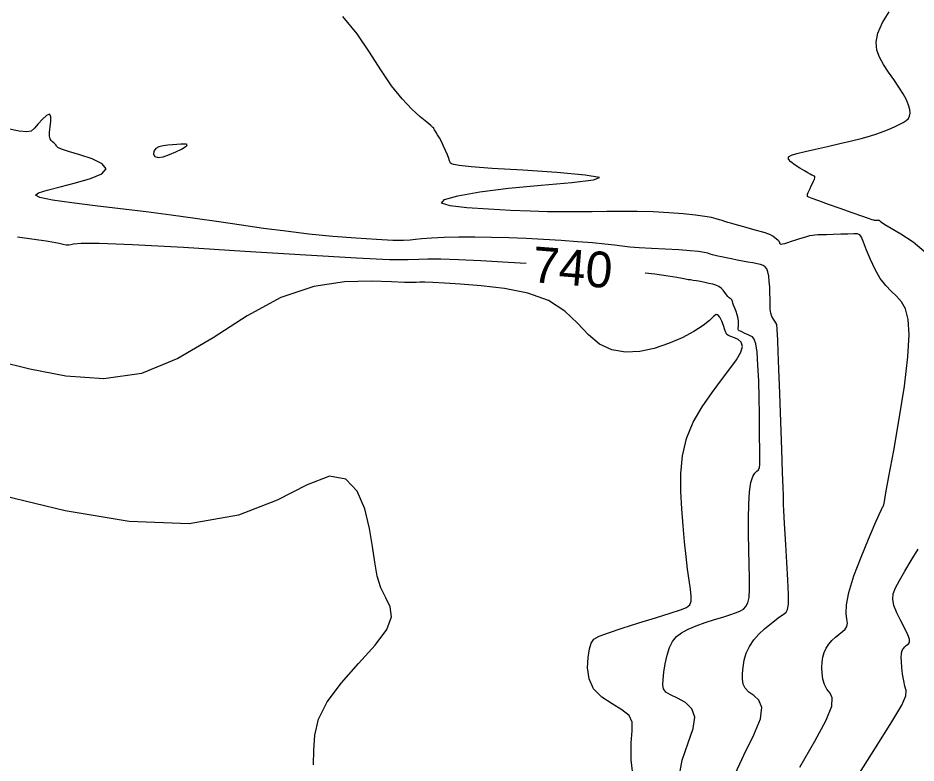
# Model space of a CAD drawing. Extents: x 2566142 to 2571431, y 418755 to 421584.
# Drawn here: x 2568835 to 2569337, y 419171 to 419587 of the extents above; entities that cross this region are included whole.
import ezdxf

# ---------------------------------------------------------------- set-up
doc = ezdxf.new("R2010")
doc.units = 0
for name, color, linetype in [('Contour_ADS_Label_Major', 7, 'Continuous'), ('Contour_ADS_Major', 7, 'Continuous'), ('Contour_ADS_Minor', 7, 'Continuous')]:
    doc.layers.add(name, color=color, linetype=linetype)

msp = doc.modelspace()

# ---------------------------------------------------------------- linework, layer by layer
at = {"layer": 'Contour_ADS_Major'}
for points in [[(2569118.99, 419449.78), (2569109.17, 419450.42), (2569093.74, 419451.32), (2569081.11, 419451.92), (2569071.25, 419452.23), (2569064.09, 419452.25), (2569059, 419452.02), (2569053.04, 419451.82), (2569042.65, 419451.97), (2569024.29, 419452.79), (2568995.96, 419454.45), (2568961.85, 419456.6), (2568927.68, 419458.72), (2568899.18, 419460.31), (2568880.63, 419460.99), (2568870.61, 419460.98), (2568866.27, 419460.6), (2568864.73, 419460.2), (2568863.6, 419460.06), (2568862.26, 419460.18), (2568860.55, 419460.5), (2568858.33, 419460.99), (2568855.34, 419461.6), (2568850.94, 419462.36), (2568844.39, 419463.33), (2568834.95, 419464.57)], [(2569200.67, 419238.82), (2569202.85, 419241.51), (2569205.68, 419243.69), (2569209.33, 419245.62), (2569213.87, 419247.5), (2569218.93, 419249.31), (2569224.04, 419250.98), (2569228.75, 419252.44), (2569232.66, 419253.64), (2569235.81, 419254.69), (2569238.29, 419255.71), (2569240.21, 419256.83), (2569241.68, 419258.23), (2569242.73, 419260.28), (2569243.4, 419263.37), (2569243.71, 419267.9), (2569243.73, 419274.14), (2569243.55, 419281.72), (2569243.29, 419290.15), (2569243.09, 419298.91), (2569243.03, 419307.51), (2569243.2, 419315.46), (2569243.63, 419322.29), (2569244.37, 419327.53), (2569245.43, 419330.89), (2569246.64, 419332.79), (2569247.82, 419333.86), (2569248.74, 419334.72), (2569249.26, 419335.9), (2569249.45, 419337.61), (2569249.45, 419339.95), (2569249.38, 419343.06), (2569249.34, 419347.05), (2569249.32, 419352.08), (2569249.29, 419358.32), (2569249.2, 419365.95), (2569249.04, 419374.91), (2569248.78, 419384.34), (2569248.39, 419393.16), (2569247.87, 419400.29), (2569247.19, 419404.96), (2569246.33, 419407.58), (2569245.28, 419408.86), (2569244.03, 419409.53), (2569242.57, 419410.17), (2569241.06, 419410.84), (2569239.66, 419411.47), (2569238.54, 419411.98), (2569237.82, 419412.34), (2569237.45, 419412.64), (2569237.33, 419413.03), (2569237.39, 419413.65), (2569237.51, 419414.61), (2569237.6, 419415.88), (2569237.57, 419417.43), (2569237.33, 419419.2), (2569236.81, 419421.13), (2569236.13, 419423.1), (2569235.41, 419424.94), (2569234.81, 419426.51), (2569234.42, 419427.7), (2569234.18, 419428.55), (2569233.99, 419429.15), (2569233.75, 419429.57), (2569233.36, 419429.89), (2569232.85, 419430.23), (2569232.24, 419430.71), (2569231.54, 419431.42), (2569230.79, 419432.45), (2569229.95, 419433.68), (2569228.97, 419434.95), (2569227.83, 419436.1), (2569226.48, 419437), (2569224.9, 419437.7), (2569223.09, 419438.26), (2569221.02, 419438.76), (2569218.72, 419439.25), (2569216.36, 419439.72), (2569214.13, 419440.13), (2569212.23, 419440.45), (2569210.76, 419440.65), (2569209.48, 419440.82), (2569208.01, 419441.04), (2569206.02, 419441.41), (2569203.05, 419442.01), (2569198.26, 419442.84), (2569190.73, 419443.87), (2569185.45, 419444.45)], [(2569203.93, 419161.21), (2569206.14, 419172.49), (2569209.32, 419182.14), (2569212.11, 419190.14), (2569213.15, 419196.49), (2569211.48, 419201.21), (2569207.88, 419204.61), (2569203.51, 419207.05), (2569199.57, 419208.9), (2569196.98, 419210.51), (2569195.65, 419212.25), (2569195.25, 419214.46), (2569195.43, 419217.49), (2569195.9, 419221.56), (2569196.64, 419226.26), (2569197.66, 419231.05), (2569198.99, 419235.37), (2569200.67, 419238.82)]]:
    msp.add_lwpolyline(points, dxfattribs=at)
at = {"layer": 'Contour_ADS_Minor'}
for points in [[(2569318.23, 419523.57), (2569321.54, 419524.88), (2569324.57, 419526.2), (2569327.22, 419527.48), (2569329.44, 419528.68), (2569331.14, 419529.79), (2569332.34, 419530.92), (2569333.06, 419532.21), (2569333.33, 419533.8), (2569333.14, 419535.8), (2569332.46, 419538.26), (2569331.23, 419541.18), (2569329.4, 419544.56), (2569326.97, 419548.4), (2569324.15, 419552.53), (2569321.23, 419556.78), (2569318.48, 419560.96), (2569316.2, 419564.99), (2569314.68, 419569.06), (2569314.28, 419573.48), (2569315.31, 419578.54), (2569317.93, 419584.37), (2569321.59, 419590.46)], [(2569097.87, 419480.13), (2569085.9, 419480.97), (2569076.47, 419482.11), (2569071.74, 419483.62), (2569073.35, 419485.51), (2569080.8, 419487.64), (2569093.04, 419489.82), (2569109.05, 419491.86), (2569127.32, 419493.61), (2569144.45, 419495.14), (2569156.59, 419496.53), (2569159.88, 419497.88), (2569151.91, 419499.26), (2569136.05, 419500.62), (2569117.12, 419501.89), (2569099.95, 419503), (2569088.28, 419503.89), (2569081.64, 419504.59), (2569078.51, 419505.12), (2569077.34, 419505.54), (2569076.82, 419505.91), (2569076.53, 419506.4), (2569076.26, 419507.21), (2569075.82, 419508.54), (2569075.04, 419510.51), (2569074.01, 419512.91), (2569072.84, 419515.47), (2569071.64, 419517.9), (2569070.53, 419519.97), (2569069.55, 419521.64), (2569068.74, 419522.94), (2569068.14, 419523.87), (2569067.77, 419524.47), (2569067.57, 419524.81), (2569067.49, 419525), (2569067.47, 419525.14), (2569067.4, 419525.34), (2569066.95, 419525.85), (2569065.77, 419526.92), (2569063.5, 419528.82), (2569059.89, 419531.8), (2569055.18, 419536.05), (2569049.73, 419541.74), (2569043.89, 419549.04), (2569037.91, 419557.97), (2569031.59, 419567.92), (2569024.6, 419578.12), (2569016.63, 419587.8)], [(2568892.59, 419480.42), (2568878.39, 419482.13), (2568865.29, 419483.77), (2568854.58, 419485.31), (2568847.53, 419486.74), (2568845.09, 419488.07), (2568846.73, 419489.41), (2568851.6, 419490.9), (2568858.82, 419492.68), (2568867.38, 419494.83), (2568875.68, 419497.31), (2568882, 419500), (2568884.59, 419502.8), (2568882.36, 419505.6), (2568876.72, 419508.25), (2568869.74, 419510.59), (2568863.49, 419512.46), (2568859.55, 419513.76), (2568857.62, 419514.6), (2568856.94, 419515.16), (2568856.75, 419515.61), (2568856.42, 419516.1), (2568855.88, 419516.64), (2568855.21, 419517.22), (2568854.49, 419517.83), (2568853.81, 419518.51), (2568853.26, 419519.46), (2568852.92, 419520.91), (2568852.9, 419523.11), (2568853.21, 419526.14), (2568853.55, 419529.37), (2568853.57, 419532), (2568852.89, 419533.22), (2568851.28, 419532.52), (2568849.05, 419530.43), (2568846.61, 419527.77), (2568844.42, 419525.35), (2568842.62, 419523.84), (2568840.24, 419523.34), (2568836.02, 419523.8), (2568828.71, 419525.17)], [(2569342.32, 419455.62), (2569334.98, 419461.78), (2569328.18, 419466.27), (2569322.73, 419469.41), (2569319.22, 419471.46), (2569317.36, 419472.68), (2569316.61, 419473.32), (2569316.42, 419473.62), (2569316.36, 419473.77), (2569316.31, 419473.85), (2569316.24, 419473.88), (2569316.12, 419473.88), (2569315.93, 419473.87), (2569315.67, 419473.87), (2569315.37, 419473.86), (2569315.02, 419473.86), (2569314.65, 419473.86), (2569314.27, 419473.87), (2569313.88, 419473.89), (2569313.5, 419473.93), (2569313.05, 419474.02), (2569312.08, 419474.32), (2569310.05, 419475.01), (2569306.42, 419476.29), (2569300.92, 419478.23), (2569294.35, 419480.55), (2569287.79, 419482.88), (2569282.31, 419484.82), (2569278.72, 419486.09), (2569276.8, 419486.86), (2569276.03, 419487.36), (2569275.94, 419487.85), (2569276.11, 419488.54), (2569276.44, 419489.44), (2569276.91, 419490.55), (2569277.48, 419491.81), (2569278.15, 419493.21), (2569278.82, 419494.62), (2569279.42, 419495.91), (2569279.88, 419496.96), (2569280.13, 419497.68), (2569280.21, 419498.1), (2569280.16, 419498.33), (2569280.05, 419498.45), (2569279.92, 419498.54), (2569279.73, 419498.64), (2569279.46, 419498.77), (2569279.07, 419498.96), (2569278.49, 419499.25), (2569277.61, 419499.72), (2569276.28, 419500.45), (2569274.36, 419501.55), (2569271.81, 419503.05), (2569269.09, 419504.78), (2569266.76, 419506.54), (2569265.4, 419508.11), (2569265.47, 419509.36), (2569267.05, 419510.38), (2569270.12, 419511.35), (2569274.65, 419512.44), (2569280.52, 419513.76), (2569287.21, 419515.26), (2569294.08, 419516.82), (2569300.51, 419518.34), (2569306.01, 419519.74), (2569310.65, 419521.05), (2569314.65, 419522.31), (2569318.23, 419523.57)], [(2569254.95, 419248.27), (2569257.52, 419250.29), (2569259.7, 419251.92), (2569261.51, 419253.2), (2569262.98, 419254.21), (2569264.13, 419255.13), (2569264.94, 419256.68), (2569265.39, 419259.7), (2569265.45, 419265.03), (2569265.13, 419273.11), (2569264.56, 419282.89), (2569263.9, 419292.88), (2569263.33, 419301.64), (2569262.97, 419308.03), (2569262.78, 419312.29), (2569262.71, 419314.97), (2569262.69, 419316.62), (2569262.66, 419317.95), (2569262.58, 419320.22), (2569262.41, 419324.81), (2569262.11, 419333.12), (2569261.66, 419345.92), (2569261.12, 419361.42), (2569260.56, 419377.21), (2569260.06, 419390.88), (2569259.66, 419400.6), (2569259.38, 419406.78), (2569259.19, 419410.42), (2569259.1, 419412.53), (2569259.06, 419413.94), (2569259, 419414.99), (2569258.83, 419415.83), (2569258.44, 419416.64), (2569257.79, 419417.58), (2569256.98, 419418.75), (2569256.19, 419420.23), (2569255.57, 419422.11), (2569255.23, 419424.44), (2569255.12, 419427.16), (2569255.11, 419430.17), (2569255.09, 419433.38), (2569254.97, 419436.68), (2569254.72, 419439.88), (2569254.36, 419442.77), (2569253.89, 419445.13), (2569253.28, 419446.84), (2569252.46, 419447.98), (2569251.34, 419448.73), (2569249.84, 419449.27), (2569247.88, 419449.74), (2569245.51, 419450.19), (2569242.8, 419450.66), (2569239.83, 419451.18), (2569236.69, 419451.77), (2569233.55, 419452.39), (2569230.6, 419453), (2569228.05, 419453.54), (2569226.02, 419453.98), (2569224.4, 419454.36), (2569223.04, 419454.72), (2569221.76, 419455.1), (2569220.34, 419455.54), (2569218.34, 419456.03), (2569215.27, 419456.52), (2569210.62, 419456.99), (2569204.15, 419457.4), (2569196.59, 419457.79), (2569188.92, 419458.17), (2569182.13, 419458.58), (2569176.88, 419459.04), (2569172.56, 419459.54), (2569168.23, 419460.1), (2569162.95, 419460.71), (2569156.04, 419461.35), (2569147.71, 419462.01), (2569138.45, 419462.65), (2569128.72, 419463.24), (2569118.93, 419463.75), (2569109.22, 419464.16), (2569099.67, 419464.44), (2569090.35, 419464.55), (2569081.41, 419464.5), (2569073.22, 419464.29), (2569066.21, 419463.98), (2569060.81, 419463.59), (2569057.16, 419463.17), (2569054.16, 419462.83), (2569050.41, 419462.65), (2569044.51, 419462.74), (2569035.47, 419463.19), (2569023.93, 419463.96), (2569010.98, 419465.02), (2568997.66, 419466.32), (2568984.81, 419467.83), (2568972.36, 419469.49), (2568959.98, 419471.26), (2568947.37, 419473.09), (2568934.27, 419474.95), (2568920.72, 419476.8), (2568906.79, 419478.63), (2568892.59, 419480.42)], [(2569298.07, 419251.15), (2569297.64, 419254.38), (2569297.73, 419259.17), (2569299.03, 419266.08), (2569301.95, 419275.35), (2569305.92, 419285.8), (2569310.11, 419295.94), (2569313.69, 419304.26), (2569316.04, 419309.63), (2569317.32, 419312.51), (2569317.87, 419313.71), (2569318.07, 419314.05), (2569318.2, 419314.23), (2569318.32, 419314.4), (2569318.41, 419314.54), (2569318.49, 419314.68), (2569318.59, 419315.06), (2569318.93, 419316.9), (2569319.82, 419321.7), (2569321.51, 419330.93), (2569324.15, 419345.38), (2569327.23, 419363.09), (2569330.11, 419381.44), (2569332.13, 419397.77), (2569332.78, 419410.05), (2569332.2, 419418.64), (2569330.66, 419424.47), (2569328.42, 419428.51), (2569325.74, 419431.64), (2569322.78, 419434.47), (2569319.7, 419437.56), (2569316.64, 419441.44), (2569313.74, 419446.44), (2569311.14, 419452.01), (2569308.95, 419457.36), (2569307.3, 419461.71), (2569306.21, 419464.47), (2569305.28, 419465.89), (2569304.01, 419466.38), (2569301.89, 419466.39), (2569298.61, 419466.28), (2569294.58, 419466.15), (2569290.41, 419466.02), (2569286.68, 419465.91), (2569283.86, 419465.85), (2569281.8, 419465.79), (2569280.19, 419465.7), (2569278.74, 419465.52), (2569277.2, 419465.23), (2569275.5, 419464.81), (2569273.62, 419464.27), (2569271.54, 419463.61), (2569269.27, 419462.85), (2569266.98, 419462.08), (2569264.88, 419461.38), (2569263.18, 419460.86), (2569262.02, 419460.59), (2569261.32, 419460.54), (2569260.95, 419460.64), (2569260.76, 419460.84), (2569260.65, 419461.1), (2569260.58, 419461.37), (2569260.53, 419461.62), (2569260.49, 419461.83), (2569260.44, 419461.99), (2569260.31, 419462.16), (2569260.03, 419462.42), (2569259.54, 419462.85), (2569258.79, 419463.49), (2569257.8, 419464.28), (2569256.64, 419465.11), (2569255.35, 419465.87), (2569253.96, 419466.49), (2569252.32, 419467.03), (2569250.26, 419467.61), (2569247.6, 419468.32), (2569244.26, 419469.22), (2569240.57, 419470.24), (2569236.96, 419471.26), (2569233.85, 419472.15), (2569231.55, 419472.83), (2569229.85, 419473.36), (2569228.42, 419473.81), (2569226.93, 419474.29), (2569225.05, 419474.86), (2569222.42, 419475.5), (2569218.69, 419476.18), (2569213.51, 419476.88), (2569206.69, 419477.55), (2569198.61, 419478.15), (2569189.84, 419478.62), (2569180.93, 419478.91), (2569172.31, 419478.98), (2569163.98, 419478.9), (2569155.83, 419478.77), (2569147.74, 419478.66), (2569139.53, 419478.67), (2569130.83, 419478.8), (2569121.2, 419479.08), (2569110.21, 419479.52), (2569097.87, 419480.13)], [(2569161.27, 419207.71), (2569156.65, 419212.31), (2569154.08, 419217.94), (2569153.24, 419224.03), (2569153.52, 419229.85), (2569154.31, 419234.64), (2569155.2, 419237.91), (2569156.74, 419240.07), (2569159.7, 419241.76), (2569164.85, 419243.64), (2569172.57, 419246.17), (2569181.84, 419249.11), (2569191.22, 419252.05), (2569199.32, 419254.56), (2569205.04, 419256.36), (2569208.57, 419257.78), (2569210.43, 419259.25), (2569211.13, 419261.25), (2569211.14, 419264.14), (2569210.69, 419268.05), (2569209.94, 419273.03), (2569209.06, 419279.11), (2569208.21, 419286.3), (2569207.4, 419294.44), (2569206.65, 419303.34), (2569205.95, 419312.78), (2569205.39, 419322.58), (2569205.32, 419332.52), (2569206.18, 419342.41), (2569208.4, 419352.05), (2569212.25, 419361.26), (2569217.24, 419369.88), (2569222.74, 419377.79), (2569228.1, 419384.86), (2569232.74, 419390.99), (2569236.36, 419396.15), (2569238.75, 419400.34), (2569239.67, 419403.56), (2569239.05, 419405.85), (2569237.35, 419407.39), (2569235.2, 419408.39), (2569233.21, 419409.05), (2569231.86, 419409.6), (2569231.04, 419410.26), (2569230.47, 419411.27), (2569229.89, 419412.86), (2569229.11, 419415.14), (2569228.15, 419417.67), (2569227.1, 419419.9), (2569226.05, 419421.27), (2569225, 419421.34), (2569223.58, 419420.21), (2569221.32, 419418.11), (2569217.75, 419415.26), (2569212.56, 419411.91), (2569206.01, 419408.42), (2569198.52, 419405.15), (2569190.51, 419402.47), (2569182.37, 419400.76), (2569174.4, 419400.34), (2569166.84, 419401.57), (2569159.96, 419404.76), (2569153.82, 419410.04), (2569147.66, 419416.56), (2569140.52, 419423.27), (2569131.43, 419429.1), (2569119.84, 419433.25), (2569106.81, 419435.89), (2569093.79, 419437.43), (2569082.26, 419438.31), (2569073.35, 419438.87), (2569066.92, 419439.21), (2569062.48, 419439.37), (2569059.58, 419439.38), (2569057.56, 419439.3), (2569055.2, 419439.22), (2569051.09, 419439.27), (2569043.82, 419439.6), (2569032.42, 419440.07), (2569017.57, 419439.65), (2569000.39, 419437.02), (2568981.98, 419430.9), (2568963.25, 419420.66), (2568944.18, 419408.36), (2568924.58, 419396.71), (2568904.23, 419388.43), (2568883.12, 419385.51), (2568862.01, 419386.88), (2568841.88, 419390.76), (2568823.69, 419395.34)], [(2569035.85, 419275.26), (2569034.5, 419282.99), (2569033.23, 419291.88), (2569031.52, 419301.94), (2569028.84, 419312.79), (2569024.61, 419322.67), (2569018.23, 419329.46), (2569009.12, 419331.03), (2568996.65, 419326.24), (2568980, 419317.77), (2568958.32, 419309.26), (2568930.76, 419304.39), (2568897.35, 419305.74), (2568861.55, 419311.78), (2568827.75, 419319.9)], [(2569331.94, 419237.09), (2569332.61, 419237.7), (2569333.01, 419238.57), (2569332.88, 419240.04), (2569332.01, 419242.46), (2569330.29, 419246.01), (2569328.1, 419250.31), (2569325.94, 419254.8), (2569324.31, 419258.94), (2569323.61, 419262.35), (2569323.91, 419265.43), (2569325.15, 419268.72), (2569327.3, 419272.78), (2569330.28, 419277.99), (2569333.86, 419284.02), (2569337.78, 419290.32)], [(2569000.19, 419169.92), (2569000.36, 419178.04), (2569000.94, 419186.44), (2569003.05, 419195.38), (2569007.81, 419205.1), (2569015.81, 419215.66), (2569025.46, 419226.44), (2569034.66, 419236.65), (2569041.28, 419245.5), (2569043.81, 419252.45), (2569043.1, 419258.08), (2569040.62, 419263.22), (2569037.83, 419268.72), (2569035.85, 419275.26)], [(2569271.7, 419168.54), (2569280.09, 419183.01), (2569286.51, 419194.75), (2569289.56, 419202.56), (2569289.89, 419207.21), (2569288.6, 419209.98), (2569286.82, 419212.15), (2569285.48, 419214.73), (2569284.65, 419217.75), (2569284.24, 419220.99), (2569284.12, 419224.22), (2569284.23, 419227.25), (2569284.59, 419230.05), (2569285.28, 419232.65), (2569286.36, 419235.06), (2569287.88, 419237.29), (2569289.7, 419239.34), (2569291.68, 419241.19), (2569293.66, 419242.83), (2569295.48, 419244.28), (2569296.98, 419245.67), (2569298, 419247.16), (2569298.37, 419248.91), (2569298.07, 419251.15)], [(2569234.66, 419162.77), (2569240.51, 419175.34), (2569246.1, 419186.58), (2569249.83, 419195.62), (2569250.52, 419201.88), (2569248.88, 419205.91), (2569246.06, 419208.52), (2569243.2, 419210.52), (2569241.23, 419212.62), (2569240.15, 419215), (2569239.74, 419217.73), (2569239.77, 419220.86), (2569240.08, 419224.42), (2569240.73, 419228.26), (2569241.87, 419232.2), (2569243.62, 419236.05), (2569246.06, 419239.64), (2569248.95, 419242.9), (2569252.01, 419245.79), (2569254.95, 419248.27)], [(2569302.88, 419161.74), (2569314.08, 419179.44), (2569323.19, 419193.88), (2569328.6, 419203.23), (2569330.89, 419208.51), (2569331.14, 419211.45), (2569330.45, 419213.77), (2569329.72, 419216.84), (2569329.15, 419220.51), (2569328.73, 419224.26), (2569328.47, 419227.58), (2569328.37, 419230.08), (2569328.44, 419231.85), (2569328.68, 419233.11), (2569329.1, 419234.08), (2569329.69, 419234.94), (2569330.4, 419235.74), (2569331.17, 419236.46), (2569331.94, 419237.09)], [(2569179.09, 419159.97), (2569177.67, 419172.7), (2569177.62, 419182.21), (2569178.14, 419188.94), (2569178.12, 419193.71), (2569176.47, 419197.35), (2569172.45, 419200.61), (2569166.96, 419203.94), (2569161.27, 419207.71)]]:
    msp.add_lwpolyline(points, dxfattribs=at)
msp.add_lwpolyline([(2568929.16, 419516.54), (2568927.94, 419516.59), (2568926.19, 419516.5), (2568924.02, 419516.33), (2568921.55, 419516.13), (2568918.91, 419515.93), (2568916.31, 419515.61), (2568913.98, 419515.02), (2568912.18, 419514.02), (2568911.12, 419512.54), (2568910.92, 419510.93), (2568911.68, 419509.62), (2568913.52, 419509.04), (2568916.42, 419509.47), (2568919.93, 419510.68), (2568923.48, 419512.24), (2568926.49, 419513.78), (2568928.52, 419514.97), (2568929.57, 419515.79), (2568929.74, 419516.29), (2568929.16, 419516.54)], close=True, dxfattribs=at)

# ---------------------------------------------------------------- texts
at = {"layer": 'Contour_ADS_Label_Major'}
msp.add_text('740', height=20, rotation=355.4144, dxfattribs=at).set_placement((2569121.79, 419439.52))

doc.saveas('drawing.dxf')
